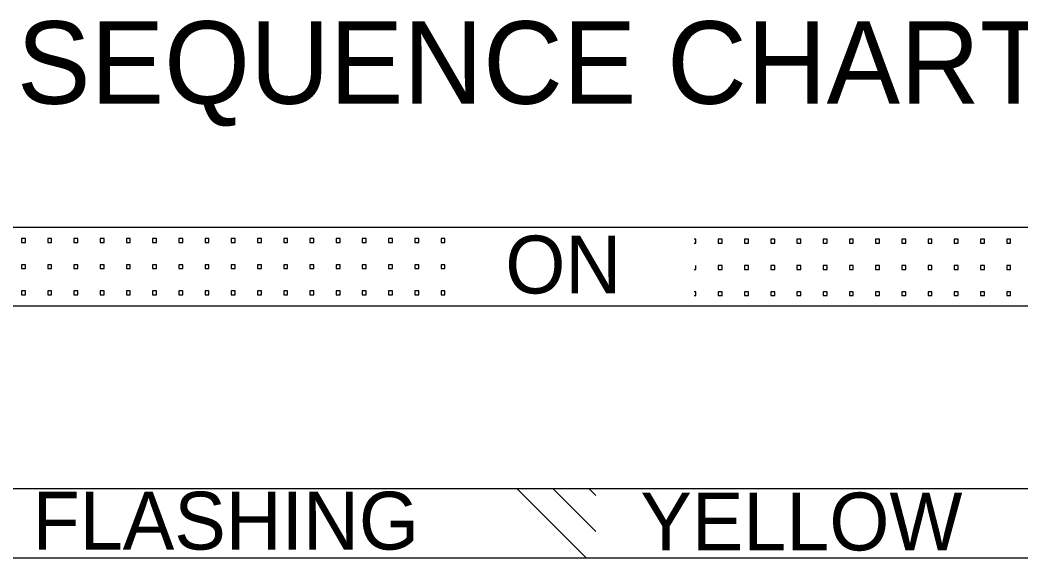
# Model space of a CAD drawing. Extents: x 10000 to 10825, y 10000 to 10530.
# Drawn here: x 10609.2 to 10669.9, y 10165.2 to 10197.8 of the extents above; entities that cross this region are included whole.
import ezdxf

# ---------------------------------------------------------------- set-up
doc = ezdxf.new("R2010")
doc.units = 0
doc.layers.add('Default', color=7, linetype='Continuous')
doc.layers.add('TextStructures', color=7, linetype='Continuous')

msp = doc.modelspace()

# ---------------------------------------------------------------- linework, layer by layer
at = {"layer": 'Default'}
for p, q in [((10784.11, 10185.22), (10490.187, 10185.22)), ((10490.187, 10180.482), (10784.11, 10180.482)), ((10490.187, 10169.414), (10784.11, 10169.414)), ((10490.187, 10165.202), (10784.11, 10165.202))]:
    msp.add_line(p, q, dxfattribs=at)
for points in [[(10609.56, 10184.317), (10609.56, 10184.555), (10609.323, 10184.554), (10609.323, 10184.317), (10609.56, 10184.317)], [(10609.56, 10184.317), (10609.56, 10184.555), (10609.323, 10184.554), (10609.323, 10184.317), (10609.56, 10184.317)], [(10611.146, 10184.317), (10611.146, 10184.555), (10610.909, 10184.554), (10610.909, 10184.317), (10611.146, 10184.317)], [(10611.146, 10184.317), (10611.146, 10184.555), (10610.909, 10184.554), (10610.909, 10184.317), (10611.146, 10184.317)], [(10612.736, 10184.317), (10612.736, 10184.555), (10612.499, 10184.554), (10612.499, 10184.317), (10612.736, 10184.317)], [(10612.736, 10184.317), (10612.736, 10184.555), (10612.499, 10184.554), (10612.499, 10184.317), (10612.736, 10184.317)], [(10614.322, 10184.317), (10614.322, 10184.555), (10614.086, 10184.554), (10614.086, 10184.317), (10614.322, 10184.317)], [(10614.322, 10184.317), (10614.322, 10184.555), (10614.086, 10184.554), (10614.086, 10184.317), (10614.322, 10184.317)], [(10615.912, 10184.317), (10615.912, 10184.555), (10615.675, 10184.554), (10615.675, 10184.317), (10615.912, 10184.317)], [(10615.912, 10184.317), (10615.912, 10184.555), (10615.675, 10184.554), (10615.675, 10184.317), (10615.912, 10184.317)], [(10617.498, 10184.317), (10617.498, 10184.555), (10617.262, 10184.554), (10617.262, 10184.317), (10617.498, 10184.317)], [(10617.498, 10184.317), (10617.498, 10184.555), (10617.262, 10184.554), (10617.262, 10184.317), (10617.498, 10184.317)], [(10619.088, 10184.317), (10619.088, 10184.555), (10618.852, 10184.554), (10618.852, 10184.317), (10619.088, 10184.317)], [(10619.088, 10184.317), (10619.088, 10184.555), (10618.852, 10184.554), (10618.852, 10184.317), (10619.088, 10184.317)], [(10620.675, 10184.317), (10620.675, 10184.555), (10620.438, 10184.554), (10620.438, 10184.317), (10620.675, 10184.317)], [(10620.675, 10184.317), (10620.675, 10184.555), (10620.438, 10184.554), (10620.438, 10184.317), (10620.675, 10184.317)], [(10622.264, 10184.317), (10622.264, 10184.555), (10622.028, 10184.554), (10622.028, 10184.317), (10622.264, 10184.317)], [(10622.264, 10184.317), (10622.264, 10184.555), (10622.028, 10184.554), (10622.028, 10184.317), (10622.264, 10184.317)], [(10623.851, 10184.317), (10623.851, 10184.555), (10623.614, 10184.554), (10623.614, 10184.317), (10623.851, 10184.317)], [(10623.851, 10184.317), (10623.851, 10184.555), (10623.614, 10184.554), (10623.614, 10184.317), (10623.851, 10184.317)], [(10625.441, 10184.317), (10625.441, 10184.555), (10625.204, 10184.554), (10625.204, 10184.317), (10625.441, 10184.317)], [(10625.441, 10184.317), (10625.441, 10184.555), (10625.204, 10184.554), (10625.204, 10184.317), (10625.441, 10184.317)], [(10627.027, 10184.317), (10627.027, 10184.555), (10626.79, 10184.554), (10626.79, 10184.317), (10627.027, 10184.317)], [(10627.027, 10184.317), (10627.027, 10184.555), (10626.79, 10184.554), (10626.79, 10184.317), (10627.027, 10184.317)], [(10628.617, 10184.317), (10628.617, 10184.555), (10628.38, 10184.554), (10628.38, 10184.317), (10628.617, 10184.317)], [(10628.617, 10184.317), (10628.617, 10184.555), (10628.38, 10184.554), (10628.38, 10184.317), (10628.617, 10184.317)], [(10630.203, 10184.317), (10630.203, 10184.555), (10629.966, 10184.554), (10629.966, 10184.317), (10630.203, 10184.317)], [(10630.203, 10184.317), (10630.203, 10184.555), (10629.966, 10184.554), (10629.966, 10184.317), (10630.203, 10184.317)], [(10631.793, 10184.317), (10631.793, 10184.555), (10631.556, 10184.554), (10631.556, 10184.317), (10631.793, 10184.317)], [(10631.793, 10184.317), (10631.793, 10184.555), (10631.556, 10184.554), (10631.556, 10184.317), (10631.793, 10184.317)], [(10633.379, 10184.317), (10633.379, 10184.555), (10633.143, 10184.554), (10633.143, 10184.317), (10633.379, 10184.317)], [(10633.379, 10184.317), (10633.379, 10184.555), (10633.143, 10184.554), (10633.143, 10184.317), (10633.379, 10184.317)], [(10634.969, 10184.317), (10634.969, 10184.555), (10634.732, 10184.554), (10634.732, 10184.317), (10634.969, 10184.317)], [(10634.969, 10184.317), (10634.969, 10184.555), (10634.732, 10184.554), (10634.732, 10184.317), (10634.969, 10184.317)], [(10650.177, 10184.507), (10650.073, 10184.506)], [(10650.073, 10184.267), (10650.177, 10184.267)], [(10650.177, 10184.267), (10650.177, 10184.507)], [(10651.767, 10184.267), (10651.767, 10184.507), (10651.53, 10184.506), (10651.53, 10184.267), (10651.767, 10184.267)], [(10651.767, 10184.267), (10651.767, 10184.507), (10651.53, 10184.506), (10651.53, 10184.267), (10651.767, 10184.267)], [(10653.353, 10184.267), (10653.353, 10184.507), (10653.117, 10184.506), (10653.117, 10184.267), (10653.353, 10184.267)], [(10653.353, 10184.267), (10653.353, 10184.507), (10653.117, 10184.506), (10653.117, 10184.267), (10653.353, 10184.267)], [(10654.943, 10184.267), (10654.943, 10184.507), (10654.707, 10184.506), (10654.707, 10184.267), (10654.943, 10184.267)], [(10654.943, 10184.267), (10654.943, 10184.507), (10654.707, 10184.506), (10654.707, 10184.267), (10654.943, 10184.267)], [(10656.53, 10184.267), (10656.53, 10184.507), (10656.293, 10184.506), (10656.293, 10184.267), (10656.53, 10184.267)], [(10656.53, 10184.267), (10656.53, 10184.507), (10656.293, 10184.506), (10656.293, 10184.267), (10656.53, 10184.267)], [(10658.119, 10184.267), (10658.119, 10184.507), (10657.883, 10184.506), (10657.883, 10184.267), (10658.119, 10184.267)], [(10658.119, 10184.267), (10658.119, 10184.507), (10657.883, 10184.506), (10657.883, 10184.267), (10658.119, 10184.267)], [(10659.706, 10184.267), (10659.706, 10184.507), (10659.469, 10184.506), (10659.469, 10184.267), (10659.706, 10184.267)], [(10659.706, 10184.267), (10659.706, 10184.507), (10659.469, 10184.506), (10659.469, 10184.267), (10659.706, 10184.267)], [(10661.295, 10184.267), (10661.295, 10184.507), (10661.059, 10184.506), (10661.059, 10184.267), (10661.295, 10184.267)], [(10661.295, 10184.267), (10661.295, 10184.507), (10661.059, 10184.506), (10661.059, 10184.267), (10661.295, 10184.267)], [(10662.882, 10184.267), (10662.882, 10184.507), (10662.645, 10184.506), (10662.645, 10184.267), (10662.882, 10184.267)], [(10662.882, 10184.267), (10662.882, 10184.507), (10662.645, 10184.506), (10662.645, 10184.267), (10662.882, 10184.267)], [(10664.472, 10184.267), (10664.472, 10184.507), (10664.235, 10184.506), (10664.235, 10184.267), (10664.472, 10184.267)], [(10664.472, 10184.267), (10664.472, 10184.507), (10664.235, 10184.506), (10664.235, 10184.267), (10664.472, 10184.267)], [(10666.058, 10184.267), (10666.058, 10184.507), (10665.821, 10184.506), (10665.821, 10184.267), (10666.058, 10184.267)], [(10666.058, 10184.267), (10666.058, 10184.507), (10665.821, 10184.506), (10665.821, 10184.267), (10666.058, 10184.267)], [(10667.648, 10184.267), (10667.648, 10184.507), (10667.411, 10184.506), (10667.411, 10184.267), (10667.648, 10184.267)], [(10667.648, 10184.267), (10667.648, 10184.507), (10667.411, 10184.506), (10667.411, 10184.267), (10667.648, 10184.267)], [(10669.234, 10184.267), (10669.234, 10184.507), (10668.998, 10184.506), (10668.998, 10184.267), (10669.234, 10184.267)], [(10669.234, 10184.267), (10669.234, 10184.507), (10668.998, 10184.506), (10668.998, 10184.267), (10669.234, 10184.267)], [(10609.56, 10182.728), (10609.56, 10182.967), (10609.323, 10182.966), (10609.323, 10182.728), (10609.56, 10182.728)], [(10609.56, 10182.728), (10609.56, 10182.967), (10609.323, 10182.966), (10609.323, 10182.728), (10609.56, 10182.728)], [(10611.146, 10182.728), (10611.146, 10182.967), (10610.909, 10182.966), (10610.909, 10182.728), (10611.146, 10182.728)], [(10611.146, 10182.728), (10611.146, 10182.967), (10610.909, 10182.966), (10610.909, 10182.728), (10611.146, 10182.728)], [(10612.736, 10182.728), (10612.736, 10182.967), (10612.499, 10182.966), (10612.499, 10182.728), (10612.736, 10182.728)], [(10612.736, 10182.728), (10612.736, 10182.967), (10612.499, 10182.966), (10612.499, 10182.728), (10612.736, 10182.728)], [(10614.322, 10182.728), (10614.322, 10182.967), (10614.086, 10182.966), (10614.086, 10182.728), (10614.322, 10182.728)], [(10614.322, 10182.728), (10614.322, 10182.967), (10614.086, 10182.966), (10614.086, 10182.728), (10614.322, 10182.728)], [(10615.912, 10182.728), (10615.912, 10182.967), (10615.675, 10182.966), (10615.675, 10182.728), (10615.912, 10182.728)], [(10615.912, 10182.728), (10615.912, 10182.967), (10615.675, 10182.966), (10615.675, 10182.728), (10615.912, 10182.728)], [(10617.498, 10182.728), (10617.498, 10182.967), (10617.262, 10182.966), (10617.262, 10182.728), (10617.498, 10182.728)], [(10617.498, 10182.728), (10617.498, 10182.967), (10617.262, 10182.966), (10617.262, 10182.728), (10617.498, 10182.728)], [(10619.088, 10182.728), (10619.088, 10182.967), (10618.852, 10182.966), (10618.852, 10182.728), (10619.088, 10182.728)], [(10619.088, 10182.728), (10619.088, 10182.967), (10618.852, 10182.966), (10618.852, 10182.728), (10619.088, 10182.728)], [(10620.675, 10182.728), (10620.675, 10182.967), (10620.438, 10182.966), (10620.438, 10182.728), (10620.675, 10182.728)], [(10620.675, 10182.728), (10620.675, 10182.967), (10620.438, 10182.966), (10620.438, 10182.728), (10620.675, 10182.728)], [(10622.264, 10182.728), (10622.264, 10182.967), (10622.028, 10182.966), (10622.028, 10182.728), (10622.264, 10182.728)], [(10622.264, 10182.728), (10622.264, 10182.967), (10622.028, 10182.966), (10622.028, 10182.728), (10622.264, 10182.728)], [(10623.851, 10182.728), (10623.851, 10182.967), (10623.614, 10182.966), (10623.614, 10182.728), (10623.851, 10182.728)], [(10623.851, 10182.728), (10623.851, 10182.967), (10623.614, 10182.966), (10623.614, 10182.728), (10623.851, 10182.728)], [(10625.441, 10182.728), (10625.441, 10182.967), (10625.204, 10182.966), (10625.204, 10182.728), (10625.441, 10182.728)], [(10625.441, 10182.728), (10625.441, 10182.967), (10625.204, 10182.966), (10625.204, 10182.728), (10625.441, 10182.728)], [(10627.027, 10182.728), (10627.027, 10182.967), (10626.79, 10182.966), (10626.79, 10182.728), (10627.027, 10182.728)], [(10627.027, 10182.728), (10627.027, 10182.967), (10626.79, 10182.966), (10626.79, 10182.728), (10627.027, 10182.728)], [(10628.617, 10182.728), (10628.617, 10182.967), (10628.38, 10182.966), (10628.38, 10182.728), (10628.617, 10182.728)], [(10628.617, 10182.728), (10628.617, 10182.967), (10628.38, 10182.966), (10628.38, 10182.728), (10628.617, 10182.728)], [(10630.203, 10182.728), (10630.203, 10182.967), (10629.966, 10182.966), (10629.966, 10182.728), (10630.203, 10182.728)], [(10630.203, 10182.728), (10630.203, 10182.967), (10629.966, 10182.966), (10629.966, 10182.728), (10630.203, 10182.728)], [(10631.793, 10182.728), (10631.793, 10182.967), (10631.556, 10182.966), (10631.556, 10182.728), (10631.793, 10182.728)], [(10631.793, 10182.728), (10631.793, 10182.967), (10631.556, 10182.966), (10631.556, 10182.728), (10631.793, 10182.728)], [(10633.379, 10182.728), (10633.379, 10182.967), (10633.143, 10182.966), (10633.143, 10182.728), (10633.379, 10182.728)], [(10633.379, 10182.728), (10633.379, 10182.967), (10633.143, 10182.966), (10633.143, 10182.728), (10633.379, 10182.728)], [(10634.969, 10182.728), (10634.969, 10182.967), (10634.732, 10182.966), (10634.732, 10182.728), (10634.969, 10182.728)], [(10634.969, 10182.728), (10634.969, 10182.967), (10634.732, 10182.966), (10634.732, 10182.728), (10634.969, 10182.728)], [(10650.177, 10182.679), (10650.177, 10182.919)], [(10651.767, 10182.679), (10651.767, 10182.919), (10651.53, 10182.918), (10651.53, 10182.679), (10651.767, 10182.679)], [(10651.767, 10182.679), (10651.767, 10182.919), (10651.53, 10182.918), (10651.53, 10182.679), (10651.767, 10182.679)], [(10653.353, 10182.679), (10653.353, 10182.919), (10653.117, 10182.918), (10653.117, 10182.679), (10653.353, 10182.679)], [(10653.353, 10182.679), (10653.353, 10182.919), (10653.117, 10182.918), (10653.117, 10182.679), (10653.353, 10182.679)], [(10654.943, 10182.679), (10654.943, 10182.919), (10654.707, 10182.918), (10654.707, 10182.679), (10654.943, 10182.679)], [(10654.943, 10182.679), (10654.943, 10182.919), (10654.707, 10182.918), (10654.707, 10182.679), (10654.943, 10182.679)], [(10656.53, 10182.679), (10656.53, 10182.919), (10656.293, 10182.918), (10656.293, 10182.679), (10656.53, 10182.679)], [(10656.53, 10182.679), (10656.53, 10182.919), (10656.293, 10182.918), (10656.293, 10182.679), (10656.53, 10182.679)], [(10658.119, 10182.679), (10658.119, 10182.919), (10657.883, 10182.918), (10657.883, 10182.679), (10658.119, 10182.679)], [(10658.119, 10182.679), (10658.119, 10182.919), (10657.883, 10182.918), (10657.883, 10182.679), (10658.119, 10182.679)], [(10659.706, 10182.679), (10659.706, 10182.919), (10659.469, 10182.918), (10659.469, 10182.679), (10659.706, 10182.679)], [(10659.706, 10182.679), (10659.706, 10182.919), (10659.469, 10182.918), (10659.469, 10182.679), (10659.706, 10182.679)], [(10661.295, 10182.679), (10661.295, 10182.919), (10661.059, 10182.918), (10661.059, 10182.679), (10661.295, 10182.679)], [(10661.295, 10182.679), (10661.295, 10182.919), (10661.059, 10182.918), (10661.059, 10182.679), (10661.295, 10182.679)], [(10662.882, 10182.679), (10662.882, 10182.919), (10662.645, 10182.918), (10662.645, 10182.679), (10662.882, 10182.679)], [(10662.882, 10182.679), (10662.882, 10182.919), (10662.645, 10182.918), (10662.645, 10182.679), (10662.882, 10182.679)], [(10664.472, 10182.679), (10664.472, 10182.919), (10664.235, 10182.918), (10664.235, 10182.679), (10664.472, 10182.679)], [(10664.472, 10182.679), (10664.472, 10182.919), (10664.235, 10182.918), (10664.235, 10182.679), (10664.472, 10182.679)], [(10666.058, 10182.679), (10666.058, 10182.919), (10665.821, 10182.918), (10665.821, 10182.679), (10666.058, 10182.679)], [(10666.058, 10182.679), (10666.058, 10182.919), (10665.821, 10182.918), (10665.821, 10182.679), (10666.058, 10182.679)], [(10667.648, 10182.679), (10667.648, 10182.919), (10667.411, 10182.918), (10667.411, 10182.679), (10667.648, 10182.679)], [(10667.648, 10182.679), (10667.648, 10182.919), (10667.411, 10182.918), (10667.411, 10182.679), (10667.648, 10182.679)], [(10669.234, 10182.679), (10669.234, 10182.919), (10668.998, 10182.918), (10668.998, 10182.679), (10669.234, 10182.679)], [(10669.234, 10182.679), (10669.234, 10182.919), (10668.998, 10182.918), (10668.998, 10182.679), (10669.234, 10182.679)], [(10650.073, 10182.679), (10650.177, 10182.679)], [(10609.56, 10181.14), (10609.56, 10181.379), (10609.323, 10181.378), (10609.323, 10181.14), (10609.56, 10181.14)], [(10609.56, 10181.14), (10609.56, 10181.379), (10609.323, 10181.378), (10609.323, 10181.14), (10609.56, 10181.14)], [(10611.146, 10181.14), (10611.146, 10181.379), (10610.909, 10181.378), (10610.909, 10181.14), (10611.146, 10181.14)], [(10611.146, 10181.14), (10611.146, 10181.379), (10610.909, 10181.378), (10610.909, 10181.14), (10611.146, 10181.14)], [(10612.736, 10181.14), (10612.736, 10181.379), (10612.499, 10181.378), (10612.499, 10181.14), (10612.736, 10181.14)], [(10612.736, 10181.14), (10612.736, 10181.379), (10612.499, 10181.378), (10612.499, 10181.14), (10612.736, 10181.14)], [(10614.322, 10181.14), (10614.322, 10181.379), (10614.086, 10181.378), (10614.086, 10181.14), (10614.322, 10181.14)], [(10614.322, 10181.14), (10614.322, 10181.379), (10614.086, 10181.378), (10614.086, 10181.14), (10614.322, 10181.14)], [(10615.912, 10181.14), (10615.912, 10181.379), (10615.675, 10181.378), (10615.675, 10181.14), (10615.912, 10181.14)], [(10615.912, 10181.14), (10615.912, 10181.379), (10615.675, 10181.378), (10615.675, 10181.14), (10615.912, 10181.14)], [(10617.498, 10181.14), (10617.498, 10181.379), (10617.262, 10181.378), (10617.262, 10181.14), (10617.498, 10181.14)], [(10617.498, 10181.14), (10617.498, 10181.379), (10617.262, 10181.378), (10617.262, 10181.14), (10617.498, 10181.14)], [(10619.088, 10181.14), (10619.088, 10181.379), (10618.852, 10181.378), (10618.852, 10181.14), (10619.088, 10181.14)], [(10619.088, 10181.14), (10619.088, 10181.379), (10618.852, 10181.378), (10618.852, 10181.14), (10619.088, 10181.14)], [(10620.675, 10181.14), (10620.675, 10181.379), (10620.438, 10181.378), (10620.438, 10181.14), (10620.675, 10181.14)], [(10620.675, 10181.14), (10620.675, 10181.379), (10620.438, 10181.378), (10620.438, 10181.14), (10620.675, 10181.14)], [(10622.264, 10181.14), (10622.264, 10181.379), (10622.028, 10181.378), (10622.028, 10181.14), (10622.264, 10181.14)], [(10622.264, 10181.14), (10622.264, 10181.379), (10622.028, 10181.378), (10622.028, 10181.14), (10622.264, 10181.14)], [(10623.851, 10181.14), (10623.851, 10181.379), (10623.614, 10181.378), (10623.614, 10181.14), (10623.851, 10181.14)], [(10623.851, 10181.14), (10623.851, 10181.379), (10623.614, 10181.378), (10623.614, 10181.14), (10623.851, 10181.14)], [(10625.441, 10181.14), (10625.441, 10181.379), (10625.204, 10181.378), (10625.204, 10181.14), (10625.441, 10181.14)], [(10625.441, 10181.14), (10625.441, 10181.379), (10625.204, 10181.378), (10625.204, 10181.14), (10625.441, 10181.14)], [(10627.027, 10181.14), (10627.027, 10181.379), (10626.79, 10181.378), (10626.79, 10181.14), (10627.027, 10181.14)], [(10627.027, 10181.14), (10627.027, 10181.379), (10626.79, 10181.378), (10626.79, 10181.14), (10627.027, 10181.14)], [(10628.617, 10181.14), (10628.617, 10181.379), (10628.38, 10181.378), (10628.38, 10181.14), (10628.617, 10181.14)], [(10628.617, 10181.14), (10628.617, 10181.379), (10628.38, 10181.378), (10628.38, 10181.14), (10628.617, 10181.14)], [(10630.203, 10181.14), (10630.203, 10181.379), (10629.966, 10181.378), (10629.966, 10181.14), (10630.203, 10181.14)], [(10630.203, 10181.14), (10630.203, 10181.379), (10629.966, 10181.378), (10629.966, 10181.14), (10630.203, 10181.14)], [(10631.793, 10181.14), (10631.793, 10181.379), (10631.556, 10181.378), (10631.556, 10181.14), (10631.793, 10181.14)], [(10631.793, 10181.14), (10631.793, 10181.379), (10631.556, 10181.378), (10631.556, 10181.14), (10631.793, 10181.14)], [(10633.379, 10181.14), (10633.379, 10181.379), (10633.143, 10181.378), (10633.143, 10181.14), (10633.379, 10181.14)], [(10633.379, 10181.14), (10633.379, 10181.379), (10633.143, 10181.378), (10633.143, 10181.14), (10633.379, 10181.14)], [(10634.969, 10181.14), (10634.969, 10181.379), (10634.732, 10181.378), (10634.732, 10181.14), (10634.969, 10181.14)], [(10634.969, 10181.14), (10634.969, 10181.379), (10634.732, 10181.378), (10634.732, 10181.14), (10634.969, 10181.14)], [(10650.177, 10181.331), (10650.073, 10181.331)], [(10650.073, 10181.091), (10650.177, 10181.091)], [(10650.177, 10181.091), (10650.177, 10181.331)], [(10651.767, 10181.091), (10651.767, 10181.331), (10651.53, 10181.329), (10651.53, 10181.091), (10651.767, 10181.091)], [(10651.767, 10181.091), (10651.767, 10181.331), (10651.53, 10181.329), (10651.53, 10181.091), (10651.767, 10181.091)], [(10653.353, 10181.091), (10653.353, 10181.331), (10653.117, 10181.329), (10653.117, 10181.091), (10653.353, 10181.091)], [(10653.353, 10181.091), (10653.353, 10181.331), (10653.117, 10181.329), (10653.117, 10181.091), (10653.353, 10181.091)], [(10654.943, 10181.091), (10654.943, 10181.331), (10654.707, 10181.329), (10654.707, 10181.091), (10654.943, 10181.091)], [(10654.943, 10181.091), (10654.943, 10181.331), (10654.707, 10181.329), (10654.707, 10181.091), (10654.943, 10181.091)], [(10656.53, 10181.091), (10656.53, 10181.331), (10656.293, 10181.329), (10656.293, 10181.091), (10656.53, 10181.091)], [(10656.53, 10181.091), (10656.53, 10181.331), (10656.293, 10181.329), (10656.293, 10181.091), (10656.53, 10181.091)], [(10658.119, 10181.091), (10658.119, 10181.331), (10657.883, 10181.329), (10657.883, 10181.091), (10658.119, 10181.091)], [(10658.119, 10181.091), (10658.119, 10181.331), (10657.883, 10181.329), (10657.883, 10181.091), (10658.119, 10181.091)], [(10659.706, 10181.091), (10659.706, 10181.331), (10659.469, 10181.329), (10659.469, 10181.091), (10659.706, 10181.091)], [(10659.706, 10181.091), (10659.706, 10181.331), (10659.469, 10181.329), (10659.469, 10181.091), (10659.706, 10181.091)], [(10661.295, 10181.091), (10661.295, 10181.331), (10661.059, 10181.329), (10661.059, 10181.091), (10661.295, 10181.091)], [(10661.295, 10181.091), (10661.295, 10181.331), (10661.059, 10181.329), (10661.059, 10181.091), (10661.295, 10181.091)], [(10662.882, 10181.091), (10662.882, 10181.331), (10662.645, 10181.329), (10662.645, 10181.091), (10662.882, 10181.091)], [(10662.882, 10181.091), (10662.882, 10181.331), (10662.645, 10181.329), (10662.645, 10181.091), (10662.882, 10181.091)], [(10664.472, 10181.091), (10664.472, 10181.331), (10664.235, 10181.329), (10664.235, 10181.091), (10664.472, 10181.091)], [(10664.472, 10181.091), (10664.472, 10181.331), (10664.235, 10181.329), (10664.235, 10181.091), (10664.472, 10181.091)], [(10666.058, 10181.091), (10666.058, 10181.331), (10665.821, 10181.329), (10665.821, 10181.091), (10666.058, 10181.091)], [(10666.058, 10181.091), (10666.058, 10181.331), (10665.821, 10181.329), (10665.821, 10181.091), (10666.058, 10181.091)], [(10667.648, 10181.091), (10667.648, 10181.331), (10667.411, 10181.329), (10667.411, 10181.091), (10667.648, 10181.091)], [(10667.648, 10181.091), (10667.648, 10181.331), (10667.411, 10181.329), (10667.411, 10181.091), (10667.648, 10181.091)], [(10669.234, 10181.091), (10669.234, 10181.331), (10668.998, 10181.329), (10668.998, 10181.091), (10669.234, 10181.091)], [(10669.234, 10181.091), (10669.234, 10181.331), (10668.998, 10181.329), (10668.998, 10181.091), (10669.234, 10181.091)], [(10639.321, 10169.414), (10643.534, 10165.202)], [(10641.5, 10169.414), (10644.109, 10166.804)], [(10643.678, 10169.414), (10644.109, 10168.984)]]:
    msp.add_lwpolyline(points, dxfattribs=at)

# ---------------------------------------------------------------- texts
at = {"layer": 'TextStructures'}
msp.add_text('SEQUENCE CHART', height=5, dxfattribs=at).set_placement((10609.043, 10192.712))
for s, p in [('ON', (10638.627, 10181.226)), ('FLASHING', (10609.992, 10165.712)), ('YELLOW', (10646.805, 10165.66))]:
    msp.add_text(s, height=3.5, rotation=0.00072, dxfattribs=at).set_placement(p)

doc.saveas('drawing.dxf')
